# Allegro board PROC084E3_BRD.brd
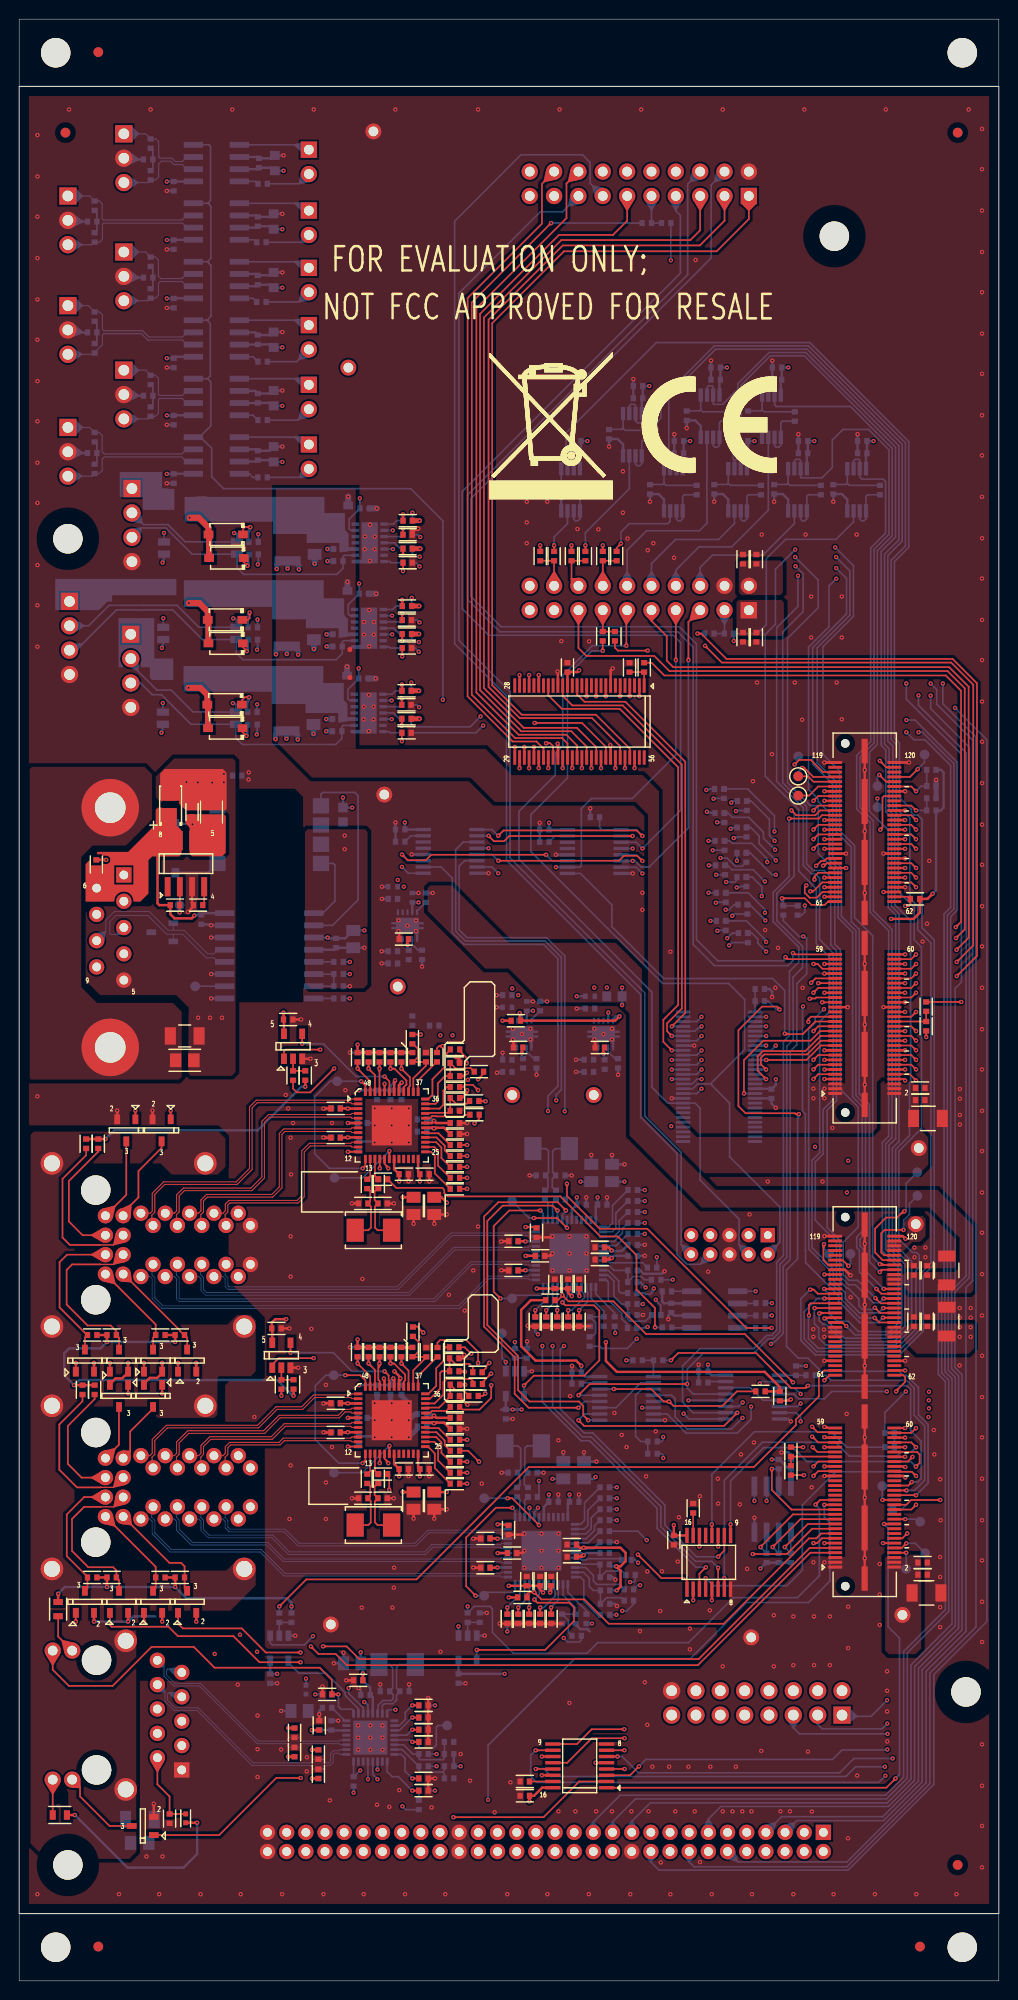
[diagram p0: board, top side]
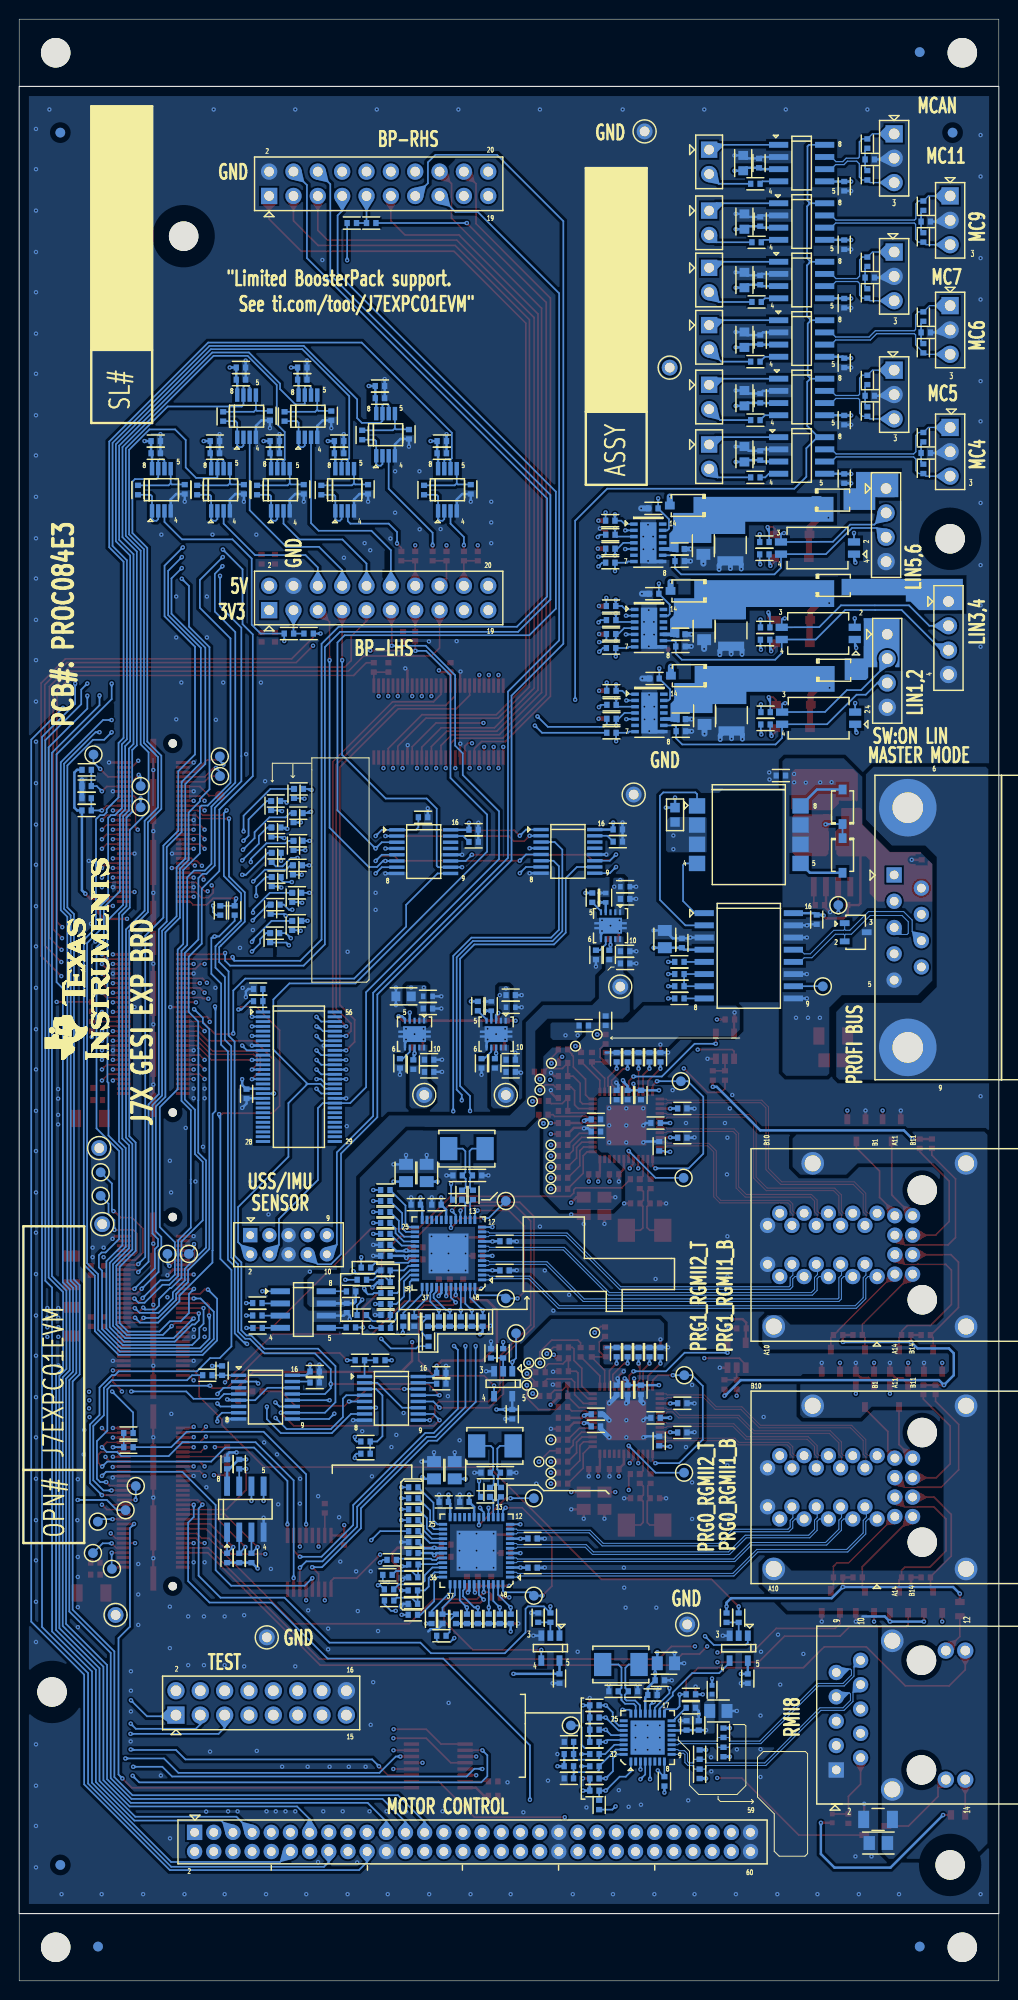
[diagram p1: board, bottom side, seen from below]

Outline 102.21 x 204.5 mm; copper layers: TOP, L02_GND1, L03_SIG1, L04_GND2, L05_PWR1, L06_SIG2, L07_GND, BOTTOM. Coordinates in mm from the lower left corner of the outline.
Outline path: rectangle 0,7 102.21,197.5 ; 0,204.5 102.21,204.5 102.21,197.5 0,197.5 0,204.5 ; 0,7 102.21,7 102.21,0 0,0 0,7

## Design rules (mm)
net group INS23889382: nets PROFIBUS_DATA_N PROFIBUS_DATA_P
net group INS23889406: nets CAN5_H CAN5_L
net group INS23889421: nets CAN6_H CAN6_L
net group INS23889438: nets CAN4_H CAN4_L
net group INS23889503: nets CAN2_H CAN2_L
net group INS23889509: nets CAN3_H CAN3_L
net group INS23889534: nets CAN1_H CAN1_L
net group INS23889562: nets PRG1_RGMII2_D0_N PRG1_RGMII2_D0_P
net group INS23889568: nets PRG1_RGMII2_D2_N PRG1_RGMII2_D2_P
net group INS23895979: nets PRG1_RGMII1_D3_N PRG1_RGMII1_D3_P
net group INS23895989: nets PRG1_RGMII1_D1_N PRG1_RGMII1_D1_P
net group INS23896047: nets PRG1_RGMII1_D0_N PRG1_RGMII1_D0_P
net group INS23896390: nets PRG0_RGMII1_D3_N PRG0_RGMII1_D3_P
net group INS23896402: nets PRG0_RGMII1_D1_N PRG0_RGMII1_D1_P
net group INS23896422: nets PRG0_RGMII1_D2_N PRG0_RGMII1_D2_P
net group INS23896856: nets PRG0_RGMII1_D0_N PRG0_RGMII1_D0_P
net group INS25431987: nets PRG1_RGMII1_D2_N PRG1_RGMII1_D2_P
net group PRG0_RGMII2_D0_: nets PRG0_RGMII2_D0_N PRG0_RGMII2_D0_P
net group PRG0_RGMII2_D1_: nets PRG0_RGMII2_D1_N PRG0_RGMII2_D1_P
net group PRG0_RGMII2_D2_: nets PRG0_RGMII2_D2_N PRG0_RGMII2_D2_P
net group PRG0_RGMII2_D3_: nets PRG0_RGMII2_D3_N PRG0_RGMII2_D3_P
net group PRG0_RGMII2_RD0: nets PRG0_RGMII2_RD0 PRG0_RGMII2_RD0_R
net group PRG1_RGMII1_RD0: nets PRG1_RGMII1_RD0 PRG1_RGMII1_RD0_R
net group PRG1_RGMII1_RD3: nets PRG1_RGMII1_RD3 PRG1_RGMII1_RD3_R
net group PRG1_RGMII2_D1_: nets PRG1_RGMII2_D1_N PRG1_RGMII2_D1_P
net group PRG1_RGMII2_D3_: nets PRG1_RGMII2_D3_N PRG1_RGMII2_D3_P
net group PRG1_RGMII2_RXC: nets PRG1_RGMII2_RXC PRG1_RGMII2_RXC_R
net group RMII8_50MHZ_REFCLK: nets RMII8_50MHZ_REFCLK RMII8_PHYAD4
net group RMII8_RXD0: nets RMII8_PHYAD1 RMII8_RXD0
net group RMII8_RXD1: nets RMII8_PHYAD2 RMII8_RXD1
net group RMII_RD: nets RMII8_MDI_RD_N RMII8_MDI_RD_P
net group RMII_TD: nets RMII8_MDI_TD_N RMII8_MDI_TD_P
net group INS23888611: nets RMII8_TXD1
net group POWER: nets PG_V2V5 V12V0_VSUP1 V12V0_VSUP2 V12V0_VSUP3 VBAT_LIN1 VBAT_LIN2 VBAT_LIN3 VPROFI_TRANSA VPROFI_TRANSB
net group PRG0_RGMII1_RD0: nets PRG0_RGMII1_RD0_R
net group PRG0_RGMII1_RD1: nets PRG0_RGMII1_RD1_R
net group PRG0_RGMII1_RD2: nets PRG0_RGMII1_RD2_R
net group PRG0_RGMII1_RD3: nets PRG0_RGMII1_RD3_R
net group PRG0_RGMII1_RX_CTL: nets PRG0_RGMII1_RX_CTL_R
net group PRG0_RGMII1_RXC: nets PRG0_RGMII1_RXC_R
net group PRG0_RGMII2_RD1: nets PRG0_RGMII2_RD1_R
net group PRG0_RGMII2_RD2: nets PRG0_RGMII2_RD2_R
net group PRG0_RGMII2_RD3: nets PRG0_RGMII2_RD3_R
net group PRG0_RGMII2_RX_CTL: nets PRG0_RGMII2_RX_CTL_R
net group PRG0_RGMII2_RXC: nets PRG0_RGMII2_RXC_R
net group PRG0_RGMII2_TD: nets PRG0_RGMII2_TD0_R PRG0_RGMII2_TD1_R PRG0_RGMII2_TD2_R PRG0_RGMII2_TD3_R PRG0_RGMII2_TX_CTL_R PRG0_RGMII2_TXC_R
net group PRG1_RGMII1_RD1: nets PRG1_RGMII1_RD1_R
net group PRG1_RGMII1_RD2: nets PRG1_RGMII1_RD2_R
net group PRG1_RGMII1_RX_CTL: nets PRG1_RGMII1_RX_CTL_R
net group PRG1_RGMII1_RXC: nets PRG1_RGMII1_RXC_R
net group PRG1_RGMII2_RD0: nets PRG1_RGMII2_RD0_R
net group PRG1_RGMII2_RD1: nets PRG1_RGMII2_RD1_R
net group PRG1_RGMII2_RD2: nets PRG1_RGMII2_RD2_R
net group PRG1_RGMII2_RD3: nets PRG1_RGMII2_RD3_R
net group PRG1_RGMII2_RX_CTL: nets PRG1_RGMII2_RX_CTL_R

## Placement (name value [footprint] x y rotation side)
C1  10uF  [CAP0402_0-75]  75.52 148.2 90 top
C2  0.1uF  [CAP0402_0-75]  76.92 148.2 270 top
C3  10uF  [CAP0402_0-75]  75.52 140.07 270 top
C4  0.1uF  [CAP0402_0-75]  76.92 140.07 90 top
C5  4.7uF_10V  [CAPT3216A_2]  15.8 122.65 90 top
C6  0.1uF  [CAP0402_0-75]  18.03 121.84 90 top
C7  10uF  [CAP0805_1-5]  20.07 121.84 90 top
C8  0.1uF  [CAP0402_0-75]  8.05 116.37 270 top
C9  0.1uF  [CAP0402_0-75]  28.07 100.22 0 top
C10  1000pF  [CAP1206_1-75]  17.27 98.5 180 top
C11  0.1uF  [CAP0402_0-75]  94.01 93.08 180 top
C12  0.1uF  [CAP0402_0-75]  94.01 91.81 180 top
C13  0.1uF  [CAP0402_0-75]  33.02 90.95 180 top
C14  22uF  [CAP1206_2]  94.82 89.91 0 top
C15  1uF  [CAP0402_0-75]  45.47 89.42 0 top
C16  1uF  [CAP0402_0-75]  45.47 88.28 0 top
C17  0.1uF  [CAP0402_0-75]  33.02 87.9 180 top
C18  0.1uF  [CAP0402_0-75]  40.13 84.09 0 top
C19  0.1uF  [CAP0402_0-75]  42.29 84.09 0 top
C20  27pF  [CAP0402_0-75]  35.89 81.04 0 top
C21  27pF  [CAP0402_0-75]  37.92 81.04 180 top
C22  10uF  [CAP0805_1-5]  41.15 80.79 270 top
C23  10uF  [CAP0805_1-5]  43.31 80.79 270 top
C24  1uF  [CAP0402_0-75]  51.56 77.1 180 top
C25  0.1uF  [CAP0402_0-75]  60.58 76.47 180 top
C26  0.1uF  [CAP0402_0-75]  54.36 75.58 0 top
C27  0.1uF  [CAP0402_0-75]  60.58 75.2 180 top
C28  1uF  [CAP0402_0-75]  51.56 74.06 180 top
C29  0.1uF  [CAP0402_0-75]  93.34 74.06 270 top
C30  0.1uF  [CAP0402_0-75]  94.74 74.06 270 top
C31  22uF  [CAP1206_2]  96.77 74.06 90 top
C32  1uF  [CAP0402_0-75]  55.88 72.66 90 top
C33  0.1uF  [CAP0402_0-75]  57.28 72.66 90 top
C34  0.1uF  [CAP0402_0-75]  58.42 72.66 90 top
C35  0.1uF  [CAP0402_0-75]  93.34 68.72 270 top
C36  0.1uF  [CAP0402_0-75]  94.74 68.72 270 top
C37  22uF  [CAP1206_2]  96.77 68.72 90 top
C38  0.1uF  [CAP0402_0-75]  26.85 68.01 0 top
C39  0.1uF  [CAP0402_0-75]  33.02 60.21 180 top
C40  1uF  [CAP0402_0-75]  45.47 58.69 0 top
C41  1uF  [CAP0402_0-75]  45.47 57.55 0 top
C42  0.1uF  [CAP0402_0-75]  33.02 57.16 180 top
C43  0.1uF  [CAP0402_0-75]  40.13 53.35 0 top
C44  0.1uF  [CAP0402_0-75]  42.29 53.35 0 top
C45  27pF  [CAP0402_0-75]  35.89 50.31 0 top
C46  27pF  [CAP0402_0-75]  37.92 50.31 180 top
C47  10uF  [CAP0805_1-5]  41.15 50.05 270 top
C48  10uF  [CAP0805_1-5]  43.31 50.05 270 top
C49  1uF  [CAP0402_0-75]  48.64 46.12 180 top
C50  0.1uF  [CAP0402_0-75]  57.66 45.48 180 top
C51  0.1uF  [CAP0402_0-75]  51.44 44.59 0 top
C52  0.1uF  [CAP0402_0-75]  57.66 44.21 180 top
C53  0.1uF  [CAP0402_0-75]  94.26 43.6 180 top
C54  1uF  [CAP0402_0-75]  48.64 43.07 180 top
C55  0.1uF  [CAP0402_0-75]  94.26 42.34 180 top
C56  1uF  [CAP0402_0-75]  52.96 41.67 90 top
C57  0.1uF  [CAP0402_0-75]  54.36 41.67 90 top
C58  0.1uF  [CAP0402_0-75]  55.5 41.67 90 top
C59  22uF  [CAP1206_2]  94.66 40.44 0 top
C60  0.01uF  [CAP0402_0-75]  35.37 31.33 180 top
C61  0.01uF  [CAP0402_0-75]  31.31 26.63 90 top
C62  4700pF  [CAP0402_0-75]  13.46 189.88 180 bottom
C63  4.7uF  [CAP0603_1]  26.67 189.5 270 bottom
C64  0.01uF  [CAP0402_0-75]  25.02 189.5 90 bottom
C65  0.1uF  [CAP0402_0-75]  16.13 187.09 270 bottom
C66  4.7uF  [CAP0603_1]  26.54 183.4 270 bottom
C67  0.01uF  [CAP0402_0-75]  24.89 183.4 90 bottom
C68  4700pF  [CAP0402_0-75]  7.62 183.4 180 bottom
C69  0.1uF  [CAP0402_0-75]  16.13 180.99 270 bottom
C70  4700pF  [CAP0402_0-75]  13.46 177.56 180 bottom
C71  4.7uF  [CAP0603_1]  26.54 177.31 270 bottom
C72  0.01uF  [CAP0402_0-75]  24.89 177.31 90 bottom
C73  0.1uF  [CAP0402_0-75]  16.13 174.89 270 bottom
C74  4700pF  [CAP0402_0-75]  7.62 171.85 180 bottom
C75  4.7uF  [CAP0603_1]  26.54 171.08 270 bottom
C76  0.01uF  [CAP0402_0-75]  24.89 171.08 90 bottom
C77  0.1uF  [CAP0402_0-75]  16.13 168.67 270 bottom
C78  0.1uF  [CAP0402_0-75]  79.07 168.19 180 bottom
C79  0.1uF  [CAP0402_0-75]  72.67 168.19 180 bottom
C80  0.01uF  [CAP0402_0-75]  79.07 166.92 180 bottom
C81  0.01uF  [CAP0402_0-75]  72.67 166.92 180 bottom
C83  0.1uF  [CAP0402_0-75]  64.57 166.26 180 bottom
C84  4700pF  [CAP0402_0-75]  13.46 165.24 180 bottom
C85  0.01uF  [CAP0402_0-75]  64.57 164.99 180 bottom
C86  4.7uF  [CAP0603_1]  26.54 164.99 270 bottom
C87  0.01uF  [CAP0402_0-75]  24.89 164.99 90 bottom
C88  0.1uF  [CAP0402_0-75]  16.13 162.7 270 bottom
C89  0.1uF  [CAP0402_0-75]  87.96 160.52 180 bottom
C90  0.1uF  [CAP0402_0-75]  81.79 160.52 180 bottom
C91  0.1uF  [CAP0402_0-75]  75.54 160.52 180 bottom
C92  0.1uF  [CAP0402_0-75]  68.83 160.52 180 bottom
C93  0.1uF  [CAP0402_0-75]  58.12 160.52 180 bottom
C94  4700pF  [CAP0402_0-75]  7.62 159.27 180 bottom
C95  0.01uF  [CAP0402_0-75]  87.96 159.25 180 bottom
C96  0.01uF  [CAP0402_0-75]  81.79 159.25 180 bottom
C97  0.01uF  [CAP0402_0-75]  75.54 159.25 180 bottom
C98  0.01uF  [CAP0402_0-75]  68.83 159.25 180 bottom
C99  0.01uF  [CAP0402_0-75]  58.12 159.25 180 bottom
C100  4.7uF  [CAP0603_1]  26.54 159.15 270 bottom
C101  0.01uF  [CAP0402_0-75]  24.89 159.02 90 bottom
C102  0.1uF  [CAP0402_0-75]  16.13 156.61 270 bottom
C107  0.1uF  [CAP0402_0-75]  39.75 120.03 180 bottom
C108  0.1uF  [CAP0402_0-75]  54.79 120 180 bottom
C109  1uF  [CAP0402_0-5]  38.99 114.06 180 bottom
C110  1uF  [CAP0402_0-5]  41.02 112.92 90 bottom
C111  0.1uF  [CAP0402_0-75]  38.99 112.79 0 bottom
C113  0.1uF  [CAP0402_0-75]  19 110.63 270 bottom
C114  10uF  [CAP0805_1-5]  34.85 108.6 270 bottom
C115  0.1uF  [CAP0402_0-75]  33.07 108.19 270 bottom
C116  10uF  [CAP0402_0-75]  38.99 107.33 180 bottom
C117  0.01uF  [CAP0402_0-75]  42.04 106.95 270 bottom
C118  0.1uF  [CAP0402_0-75]  38.99 106.06 0 bottom
C119  0.1uF  [CAP0402_0-75]  50.93 102.76 0 bottom
C120  4.7uF  [CAP0603_1]  62.1 102.63 180 bottom
C121  1uF  [CAP0402_0-5]  59.56 102.63 180 bottom
C122  1uF  [CAP0402_0-5]  52.96 101.61 90 bottom
C123  1uF  [CAP0402_0-5]  50.93 101.49 180 bottom
C124  0.1uF  [CAP0402_0-75]  59.56 101.36 0 bottom
C125  10uF  [CAP0402_0-75]  59.44 96.03 180 bottom
C126  10uF  [CAP0402_0-75]  50.93 96.03 180 bottom
C127  0.01uF  [CAP0402_0-75]  62.48 95.65 270 bottom
C128  0.01uF  [CAP0402_0-75]  53.98 95.65 270 bottom
C129  0.1uF  [CAP0402_0-75]  59.44 94.76 0 bottom
C130  0.1uF  [CAP0402_0-75]  50.93 94.76 0 bottom
C131  0.1uF  [CAP0402_0-75]  78.49 92.47 270 bottom
C132  0.1uF  [CAP0402_0-75]  39.88 92.34 270 bottom
C133  0.1uF  [CAP0402_0-75]  38.73 92.34 270 bottom
C134  1uF  [CAP0402_0-75]  37.34 92.34 270 bottom
C135  1uF  [CAP0402_0-75]  33.02 90.95 180 bottom
C136  0.1uF  [CAP0402_0-75]  42.04 89.8 180 bottom
C137  0.1uF  [CAP0402_0-75]  35.81 89.42 0 bottom
C138  0.1uF  [CAP0402_0-75]  42.04 88.53 180 bottom
C139  1uF  [CAP0402_0-75]  33.02 87.9 180 bottom
C140  10uF  [CAP0805_1-5]  61.85 84.22 90 bottom
C141  10uF  [CAP0805_1-5]  59.69 84.22 90 bottom
C142  27pF  [CAP0402_0-75]  56.46 83.96 180 bottom
C143  27pF  [CAP0402_0-75]  54.43 83.96 0 bottom
C144  0.1uF  [CAP0402_0-75]  60.83 80.91 0 bottom
C145  0.1uF  [CAP0402_0-75]  58.67 80.91 0 bottom
C146  0.1uF  [CAP0402_0-75]  51.56 77.1 180 bottom
C147  1uF  [CAP0402_0-75]  64.01 76.72 0 bottom
C148  1uF  [CAP0402_0-75]  64.01 75.58 0 bottom
C149  0.1uF  [CAP0402_0-75]  51.56 74.06 180 bottom
C150  0.1uF  [CAP0402_0-75]  68.04 70.14 270 bottom
C152  0.1uF  [CAP0402_0-75]  71.37 63.51 180 bottom
C153  0.1uF  [CAP0402_0-75]  58.17 63.39 180 bottom
C154  0.1uF  [CAP0402_0-75]  39.88 61.61 270 bottom
C155  0.1uF  [CAP0402_0-75]  38.73 61.61 270 bottom
C156  1uF  [CAP0402_0-75]  37.34 61.61 270 bottom
C157  1uF  [CAP0402_0-75]  33.02 60.21 180 bottom
C158  0.1uF  [CAP0402_0-75]  50.76 59.07 270 bottom
C159  0.1uF  [CAP0402_0-75]  42.04 59.07 180 bottom
C160  0.1uF  [CAP0402_0-75]  35.81 58.69 0 bottom
C161  0.1uF  [CAP0402_0-75]  42.04 57.8 180 bottom
C162  1uF  [CAP0402_0-75]  33.02 57.16 180 bottom
C163  0.1uF  [CAP0402_0-75]  80.52 53.86 90 bottom
C164  10uF  [CAP0805_1-5]  58.93 53.23 90 bottom
C165  10uF  [CAP0805_1-5]  56.77 53.23 90 bottom
C166  27pF  [CAP0402_0-75]  53.54 52.97 180 bottom
C167  27pF  [CAP0402_0-75]  51.51 52.97 0 bottom
C168  0.1uF  [CAP0402_0-75]  57.91 49.93 0 bottom
C169  0.1uF  [CAP0402_0-75]  55.75 49.93 0 bottom
C170  0.1uF  [CAP0402_0-75]  48.64 46.12 180 bottom
C171  1uF  [CAP0402_0-75]  61.09 45.73 0 bottom
C172  1uF  [CAP0402_0-75]  61.09 44.59 0 bottom
C173  0.1uF  [CAP0402_0-75]  48.64 43.07 180 bottom
C174  10uF  [CAP0805_1-5]  34.73 33.1 180 bottom
C175  0.1uF  [CAP0402_0-75]  45.84 31.51 270 bottom
C176  0.1uF  [CAP0402_0-75]  26.19 31.5 270 bottom
C177  1000pF  [CAP0402_0-75]  35.37 31.33 180 bottom
C178  27pF  [CAP0402_0-75]  40.2 30.18 180 bottom
C179  27pF  [CAP0402_0-75]  38.16 30.18 0 bottom
C180  100pF  [CAP0402_0-75]  36.13 29.8 180 bottom
C181  10uF  [CAP0805_1-5]  29.26 28.13 180 bottom
C182  100pF  [CAP0402_0-75]  32.58 26.63 90 bottom
C183  1000pF  [CAP0402_0-75]  31.31 26.63 90 bottom
C184  1000pF  [CAP1206_1-75]  12.6 16.82 180 bottom
C185  0.1uF  [CAP0402_0-75]  57.21 136.92 90 top
C186  1uF  [CAP0402_0-75]  28.73 25.86 270 top
C187  0.1uF  [CAP0402_0-75]  28.73 23.85 270 top
C188  0.1uF  [CAP0402_0-75]  31.22 21.58 270 top
C189  1uF  [CAP0402_0-75]  31.22 23.59 270 top
C190  1uF  [CAP0402_0-75]  15.69 16.91 270 top
C191  0.1uF  [CAP0402_0-75]  68.3 45.94 270 top
C192  0.1uF  [CAP0402_0-75]  52.76 19.29 180 top
C193  0.1uF  [CAP0402_0-75]  33.19 131.54 180 bottom
C194  1uF  [CAP0805_1-5]  30.71 131.88 270 bottom
C195  10uF  [CAP1210_2-75]  27.89 131.95 270 bottom
C196  220pF  [CAP0402_0-75]  35.92 135.77 0 bottom
C197  220pF  [CAP0402_0-75]  33.18 130.27 180 bottom
C198  0.1uF  [CAP0402_0-75]  33.23 140.37 180 bottom
C199  1uF  [CAP0805_1-5]  30.75 140.71 270 bottom
C200  10uF  [CAP1210_2-75]  27.93 140.78 270 bottom
C201  220pF  [CAP0402_0-75]  35.96 144.6 0 bottom
C202  220pF  [CAP0402_0-75]  33.22 139.11 180 bottom
C203  0.1uF  [CAP0402_0-75]  33.31 149.27 180 bottom
C204  1uF  [CAP0805_1-5]  30.83 149.61 270 bottom
C205  10uF  [CAP1210_2-75]  28.01 149.68 270 bottom
C206  220pF  [CAP0402_0-75]  36.04 153.5 0 bottom
C207  220pF  [CAP0402_0-75]  33.3 148.01 180 bottom
D4  MBR0520L  [DIO_SOD123]  16.31 122.39 90 bottom
D5  MBR0520L  [DIO_SOD123]  16.31 117.31 270 bottom
D6  SM712.TCT  [DIO_SOT23_123]  14.94 109.31 180 bottom
D7  1N4148W-7-F  [DIO_SOD123_1-4]  21.5 130.59 180 top
D8  1N4148W-7-F  [DIO_SOD123_1-4]  32.41 136.07 0 bottom
D9  1N4148W-7-F  [DIO_SOD123_1-4]  21.44 133.04 180 top
D10  1N4148W-7-F  [DIO_SOD123_1-4]  17.1 136.63 180 bottom
D11  1N4148W-7-F  [DIO_SOD123_1-4]  21.54 139.43 180 top
D12  1N4148W-7-F  [DIO_SOD123_1-4]  32.45 144.9 0 bottom
D13  1N4148W-7-F  [DIO_SOD123_1-4]  21.48 141.88 180 top
D14  1N4148W-7-F  [DIO_SOD123_1-4]  17.14 145.47 180 bottom
D15  1N4148W-7-F  [DIO_SOD123_1-4]  21.62 148.32 180 top
D16  1N4148W-7-F  [DIO_SOD123_1-4]  32.53 153.8 0 bottom
D17  1N4148W-7-F  [DIO_SOD123_1-4]  21.55 150.78 180 top
D18  1N4148W-7-F  [DIO_SOD123_1-4]  17.22 154.37 180 bottom
FL1  120E  [EMIFIL_BLM18A_0603]  33.78 121.55 270 bottom
FL2  120E  [EMIFIL_BLM15A_0402_0-6]  29.92 30.34 270 bottom
FL3  120E  [EMIFIL_BLM15A_0402_0-6]  17.37 16.94 270 top
J1  CON_PMC_2X60_M  [CON_PMC2X60_QTH-60-1-D-A_P_S_S_4-4]  88.22 109.76 90 top
J2  CON_PMC_2X60_M  [CON_PMC2X60_QTH-60-1-D-A_P_S_S_4-4]  88.22 60.38 90 top
J3  HDR_1X3  [HDR_3X1_100_S_T]  10.92 192.55 90 bottom
J4  HDR_1X2  [HDR_1X2_68002-202_S_T_8-6]  30.23 190.9 90 bottom
J5  HDR_2X10  [HDR_2X10_TSW_100_S_T]  76.13 186.07 0 bottom
J6  HDR_1X3  [HDR_3X1_100_S_T]  5.08 186.07 90 bottom
J7  HDR_1X2  [HDR_1X2_68002-202_S_T_8-6]  30.23 184.55 90 bottom
J8  HDR_1X3  [HDR_3X1_100_S_T]  10.92 180.23 90 bottom
J9  HDR_1X2  [HDR_1X2_68002-202_S_T_8-6]  30.23 178.58 90 bottom
J10  HDR_1X3  [HDR_3X1_100_S_T]  5.08 174.64 90 bottom
J11  HDR_1X2  [HDR_1X2_68002-202_S_T_8-6]  30.23 172.61 90 bottom
J12  HDR_1X3  [HDR_3X1_100_S_T]  10.92 167.91 90 bottom
J13  HDR_1X2  [HDR_1X2_68002-202_S_T_8-6]  30.23 166.38 90 bottom
J14  HDR_1X3  [HDR_3X1_100_S_T]  5.08 161.94 90 bottom
J15  HDR_1X2  [HDR_1X2_68002-202_S_T_8-6]  30.23 160.16 90 bottom
J16  HDR_2X10  [HDR_2X10_TSW_100_S_T]  76.13 142.89 0 bottom
J18  CON_DSUB_9_S  [CON_DB9_D09S33E4GV_S_R_T]  10.92 115.28 90 bottom
J19  RECP_2X5  [RECPT_2X5_NPPN052AFCN_S_T_4-3]  78.11 77.74 180 bottom
J20  CON_RJ45-28_LPJG17512AONL  [CON_RJ45-28_LPJG17512_S_R_T_25-3]  12.7 73.42 90 bottom
J21  CON_RJ45-28_LPJG17512AONL  [CON_RJ45-28_LPJG17512_S_R_T_25-3]  12.7 48.15 90 bottom
J22  HDR_8X2  [HDR_8X2_100_S_T]  85.85 27.7 0 bottom
J23  CON_RJ45-14_LPJG16314A4NL  [CON_RJ45-14_LPJG16314A4NL_S_R_T_13-6]  16.96 21.99 90 bottom
J24  RECP_30X2  [RECPT_2X30_78-74_S_T]  83.91 15.48 0 bottom
J25  HDR_1X4  [HDR_1X4_61300411121_S_T_8-6]  11.64 140.38 90 bottom
J26  HDR_1X4  [HDR_1X4_61300411121_S_T_8-6]  5.25 143.8 90 bottom
J27  HDR_1X4  [HDR_1X4_61300411121_S_T_8-6]  11.76 155.57 90 bottom
NOREF  -  []  91.63 -76.11 0 top
NOREF#2  -  []  102.21 7 90 top
NOREF#3  -  [unnamed#2]  8.26 3.57 0 top
NOREF#4  -  [unnamed#2]  97.92 12.08 0 top
NOREF#5  -  []  323.62 104.43 0 top
NOREF#6  -  []  0 204.5 0 top
NOREF#7  -  [unnamed#2]  93.98 3.57 0 top
NOREF#8  -  [unnamed#2]  98.4 201 270 top
NOREF#9  -  []  102.21 0 90 top
NOREF#10  -  []  28.19 145.68 0 top
NOREF#11  -  []  -130.43 -16.24 0 top
NOREF#12  -  [unnamed#2]  97.92 192.67 0 top
NOREF#13  -  [unnamed#2]  8.26 201.07 0 top
NOREF#14  -  []  0 6.95 0 top
NOREF#15  -  [unnamed#2]  98.4 3.5 270 top
NOREF#16  -  [unnamed#2]  3.81 3.5 270 top
NOREF#17  -  [unnamed#2]  3.81 201 270 top
NOREF#18  -  []  31.75 -88.89 0 top
NOREF#19  -  [unnamed#2]  4.83 192.67 0 top
NOREF#20  -  [unnamed#2]  5.08 150.33 180 top
NOREF#21  -  []  0 197.6 0 top
NOREF#22  -  []  -504.19 -64.76 0 top
NOREF#23  -  [unnamed#2]  98.78 30.11 0 top
NOREF#24  -  [unnamed#2]  5.08 12.08 270 top
NOREF#25  -  [unnamed#2]  85.05 181.88 90 top
NOREF#26  -  [unnamed#2]  8.26 3.57 180 bottom
NOREF#27  -  [unnamed#2]  93.98 3.57 180 bottom
NOREF#28  -  [unnamed#2]  8.26 201.07 180 bottom
NOREF#29  -  []  98.83 133.21 90 bottom
NOREF#30  -  []  105.92 16.45 90 bottom
NOREF#31  -  [unnamed#2]  97.92 192.67 180 bottom
NOREF#32  -  [unnamed#2]  4.83 192.67 180 bottom
NOREF#33  -  [unnamed#2]  97.92 12.08 180 bottom
NOREF#34  -  []  47.24 126.77 90 bottom
Q1  BSS138-7-F  [SOT23-123_1-1]  11.18 88.66 270 top
Q2  BSS138-7-F  [SOT23-123_1-1]  14.86 88.66 270 top
Q3  BSS138-7-F  [SOT23-123_1-1]  6.86 64.66 90 top
Q4  BSS138-7-F  [SOT23-123_1-1]  10.41 64.66 90 top
Q5  BSS138-7-F  [SOT23-123_1-1]  13.97 64.66 90 top
Q6  BSS138-7-F  [SOT23-123_1-1]  17.53 64.66 90 top
Q7  BSS138-7-F  [SOT23-123_1-1]  10.41 60.97 270 top
Q8  BSS138-7-F  [SOT23-123_1-1]  13.97 60.97 270 top
Q9  BSS138-7-F  [SOT23-123_1-1]  6.86 39.51 90 top
Q10  BSS138-7-F  [SOT23-123_1-1]  10.41 39.51 90 top
Q11  BSS138-7-F  [SOT23-123_1-1]  13.97 39.51 90 top
Q12  BSS138-7-F  [SOT23-123_1-1]  17.53 39.51 90 top
Q13  BSS138-7-F  [SOT23-123_1-1]  12.9 16.14 180 top
R1  0E  [RES0402_0-5]  60.88 140.17 90 top
R2  0E  [RES0402_0-5]  62.15 140.17 90 top
R3  10K  [RES0402_0-5]  93.47 112.79 0 top
R4  100K  [RES0402_0-5]  16.26 112.14 180 top
R5  10K  [RES0402_0-5]  18.67 112.14 180 top
R6  2.87K_1%  [RES0402_0-5]  40.13 108.6 180 top
R7  10K  [RES0402_0-5]  51.82 100.09 0 top
R8  1.69K_1%  [RES0402_0-5]  52.07 97.3 180 top
R9  4.53K_1%  [RES0402_0-5]  60.58 97.3 180 top
R10  10K_1%  [RES0402_0-5]  35.31 96.28 270 top
R11  10K_1%  [RES0402_0-5]  36.45 96.28 270 top
R12  10K_1%  [RES0402_0-5]  37.59 96.28 270 top
R13  5.76K_1%  [RES0402_0-5]  38.73 96.28 270 top
R14  5.76K_1%  [RES0402_0-5]  39.88 96.28 270 top
R15  5.76K_1%  [RES0402_0-5]  41.02 96.28 270 top
R16  0E_1%  [RES0402_0-5]  41.02 98.16 270 top
R17  0E_1%  [RES0402_0-5]  43.59 96.29 270 top
R18  1M_1%  [RES0805_0-75]  17.27 95.96 180 top
R19  0E_1%  [RES0402_0-5]  45.48 97.1 180 top
R20  0E  [RES0402_0-5]  28.57 94.38 90 top
R21  10K  [RES0402_0-5]  29.84 94.38 270 top
R22  0E_1%  [RES0402_0-5]  47.97 94.78 180 top
R23  0E_1%  [RES0402_0-5]  45.47 93.17 180 top
R24  0E_1%  [RES0402_0-5]  47.48 91.72 180 top
R25  0E_1%  [RES0402_0-5]  47.51 90.29 180 top
R26  220E_1%  [RES0402_0-5]  6.99 87.26 270 top
R27  220E_1%  [RES0402_0-5]  8.26 87.26 270 top
R28  0E_1%  [RES0402_0-5]  45.47 87.14 180 top
R29  0E_1%  [RES0402_0-5]  45.47 85.99 180 top
R30  0E_1%  [RES0402_0-5]  45.47 84.85 180 top
R31  0E_1%  [RES0402_0-5]  45.47 83.71 180 top
R32  0E  [RES0402_0-5]  37.95 83.56 180 top
R33  0E  [RES0402_0-5]  36.32 83.07 90 top
R34  0E  [RES0402_0-5]  37.47 83.07 90 top
R35  0E_1%  [RES0402_0-5]  45.47 82.56 180 top
R36  11K_1%  [RES0402_0-5]  53.98 77.99 90 top
R37  2.49K_1%  [RES0402_0-5]  63.99 74.06 0 bottom
R38  10K_1%  [RES0402_0-5]  63.97 72.84 180 bottom
R39  2.49K_1%  [RES0402_0-5]  63.97 70.56 180 bottom
R40  2.49K_1%  [RES0402_0-5]  63.97 69.41 0 bottom
R41  10K  [RES0402_0-5]  55.42 70.96 180 top
R42  2.49K_1%  [RES0402_0-5]  53.85 68.72 270 top
R43  2.49K_1%  [RES0402_0-5]  54.99 68.72 270 top
R44  2.49K_1%  [RES0402_0-5]  56.13 68.72 270 top
R45  2.49K_1%  [RES0402_0-5]  57.28 68.72 270 top
R46  2.49K_1%  [RES0402_0-5]  58.42 68.72 270 top
R47  2.49K_1%  [RES0402_0-5]  60.99 68.73 270 bottom
R48  220E_1%  [RES0402_0-5]  7.62 67.32 180 top
R49  220E_1%  [RES0402_0-5]  9.65 67.32 0 top
R50  220E_1%  [RES0402_0-5]  14.73 67.32 180 top
R51  220E_1%  [RES0402_0-5]  16.76 67.32 0 top
R52  10K_1%  [RES0402_0-5]  35.31 65.55 270 top
R53  10K_1%  [RES0402_0-5]  36.45 65.55 270 top
R54  10K_1%  [RES0402_0-5]  37.59 65.55 270 top
R55  5.76K_1%  [RES0402_0-5]  38.73 65.55 270 top
R56  5.76K_1%  [RES0402_0-5]  39.88 65.55 270 top
R57  5.76K_1%  [RES0402_0-5]  41.02 65.55 270 top
R58  0E_1%  [RES0402_0-5]  41.08 67.67 270 top
R59  0E_1%  [RES0402_0-5]  43.64 65.53 270 top
R60  0E_1%  [RES0402_0-5]  45.39 66.04 180 top
R61  0E_1%  [RES0402_0-5]  47.82 63.44 180 top
R62  0E  [RES0402_0-5]  27.36 62.17 90 top
R63  10K  [RES0402_0-5]  28.63 62.17 270 top
R64  0E_1%  [RES0402_0-5]  47.84 62.21 180 top
R65  220E_1%  [RES0402_0-5]  6.6 61.61 270 top
R66  220E_1%  [RES0402_0-5]  7.87 61.61 270 top
R67  0E_1%  [RES0402_0-5]  47.4 60.98 180 top
R68  0E_1%  [RES0402_0-5]  45.47 59.83 180 top
R69  0E_1%  [RES0402_0-5]  45.47 56.4 180 top
R70  0E_1%  [RES0402_0-5]  45.47 55.26 180 top
R71  0E_1%  [RES0402_0-5]  45.47 54.12 180 top
R72  0E_1%  [RES0402_0-5]  45.47 52.97 180 top
R73  0E  [RES0402_0-5]  37.95 52.83 180 top
R74  0E  [RES0402_0-5]  36.32 52.34 90 top
R75  0E  [RES0402_0-5]  37.47 52.34 90 top
R76  0E_1%  [RES0402_0-5]  45.47 51.83 180 top
R77  11K_1%  [RES0402_0-5]  51.05 47 90 top
R78  2.49K_1%  [RES0402_0-5]  61.11 42.07 0 bottom
R79  10K_1%  [RES0402_0-5]  61.08 43.41 180 bottom
R80  220E_1%  [RES0402_0-5]  7.62 42.05 180 top
R81  220E_1%  [RES0402_0-5]  9.65 42.05 0 top
R82  220E_1%  [RES0402_0-5]  14.73 42.05 180 top
R83  220E_1%  [RES0402_0-5]  16.76 42.05 0 top
R84  10K_1%  [RES0402_0-5]  61.13 40.7 180 bottom
R85  2.49K_1%  [RES0402_0-5]  61.13 39.3 0 bottom
R86  10K  [RES0402_0-5]  52.5 39.97 180 top
R87  220E  [RES0603_0-75]  4.06 38.75 270 top
R88  2.49K_1%  [RES0402_0-5]  50.93 37.73 270 top
R89  2.49K_1%  [RES0402_0-5]  52.07 37.73 270 top
R90  2.49K_1%  [RES0402_0-5]  53.21 37.73 270 top
R91  2.49K_1%  [RES0402_0-5]  54.36 37.73 270 top
R92  2.49K_1%  [RES0402_0-5]  55.5 37.73 270 top
R93  2.49K_1%  [RES0402_0-5]  58.04 37.73 270 bottom
R94  1.96K_1%  [RES0402_0-5]  32.13 29.86 180 top
R95  2.49K_1%  [RES0402_0-5]  42.19 28.72 0 top
R96  1.96K_1%  [RES0402_0-5]  42.19 27.45 0 top
R97  1.96K_1%  [RES0402_0-5]  42.19 26.18 0 top
R98  1.96K_1%  [RES0402_0-5]  42.19 24.91 0 top
R99  1.96K_1%  [RES0402_0-5]  44.85 24.91 0 bottom
R100  2.49K_1%  [RES0402_0-5]  44.86 21.1 0 bottom
R101  2.49K_1%  [RES0402_0-5]  42.19 21.1 0 top
R102  2.49K_1%  [RES0402_0-5]  42.19 19.83 0 top
R103  220E  [RES0603_0-75]  4.24 17.29 180 top
R105  59E_1%  [RES0402_0-5]  13.72 191.53 270 bottom
R106  59E_1%  [RES0402_0-5]  13.72 188.23 270 bottom
R107  33E  [RES0402_0-5]  25.4 187.34 180 bottom
R108  59E_1%  [RES0402_0-5]  7.87 185.05 270 bottom
R109  59E_1%  [RES0402_0-5]  7.87 181.75 270 bottom
R110  33E  [RES0402_0-5]  25.27 181.24 180 bottom
R111  59E_1%  [RES0402_0-5]  13.72 179.21 270 bottom
R112  59E_1%  [RES0402_0-5]  13.72 175.91 270 bottom
R113  33E  [RES0402_0-5]  25.27 175.02 180 bottom
R114  59E_1%  [RES0402_0-5]  7.87 173.5 270 bottom
R115  59E_1%  [RES0402_0-5]  7.87 170.19 270 bottom
R117  33E  [RES0402_0-5]  25.4 168.8 180 bottom
R118  59E_1%  [RES0402_0-5]  13.72 166.89 270 bottom
R121  59E_1%  [RES0402_0-5]  13.72 163.59 270 bottom
R122  1.8K_1%  [RES0402_0-5]  76.05 163.16 270 bottom
R123  1.8K_1%  [RES0402_0-5]  69.65 163.16 270 bottom
R124  1.5K  [RES0402_0-5]  80.92 163.08 90 bottom
R125  1.5K  [RES0402_0-5]  74.52 163.08 90 bottom
R126  33E  [RES0402_0-5]  25.4 162.7 180 bottom
R127  1.8K_1%  [RES0402_0-5]  61.54 161.23 270 bottom
R128  1.5K  [RES0402_0-5]  66.42 161.15 90 bottom
R129  59E_1%  [RES0402_0-5]  7.87 160.92 270 bottom
R130  59E_1%  [RES0402_0-5]  7.87 157.62 270 bottom
R131  33E  [RES0402_0-5]  25.4 156.73 180 bottom
R132  1.8K_1%  [RES0402_0-5]  84.94 155.49 270 bottom
R133  1.8K_1%  [RES0402_0-5]  78.77 155.49 270 bottom
R134  1.8K_1%  [RES0402_0-5]  72.52 155.49 270 bottom
R135  1.8K_1%  [RES0402_0-5]  65.81 155.49 270 bottom
R136  1.8K_1%  [RES0402_0-5]  55.09 155.49 270 bottom
R137  1.5K  [RES0402_0-5]  89.81 155.41 90 bottom
R138  1.5K  [RES0402_0-5]  83.64 155.41 90 bottom
R139  1.5K  [RES0402_0-5]  77.39 155.41 90 bottom
R140  1.5K  [RES0402_0-5]  70.69 155.41 90 bottom
R141  1.5K  [RES0402_0-5]  59.97 155.41 90 bottom
R144  10K  [RES0402_0-5]  95.17 126.24 0 bottom
R148  0E  [RES0402_0-5]  74.07 140.45 180 bottom
R149  0E  [RES0402_0-5]  72.01 140.45 0 bottom
R150  10K  [RES0402_0-5]  95.17 124.55 180 bottom
R151  10K  [RES0402_0-5]  95.17 123.28 180 bottom
R152  10K  [RES0402_0-5]  95.17 122.01 0 bottom
R154  10K  [RES0402_0-5]  60.07 121.3 180 bottom
R156  10K  [RES0402_0-5]  39.75 118.76 0 bottom
R157  10K  [RES0402_0-5]  54.79 118.73 0 bottom
R158  0E  [RES0402_0-5]  22.74 125.65 180 bottom
R159  10K  [RES0402_0-5]  42.42 112.92 90 bottom
R160  3.57K_1%  [RES0402_0-5]  40.64 106.95 90 bottom
R161  0E  [RES0402_0-5]  33.32 106.22 180 bottom
R162  0E  [RES0402_0-5]  33.32 104.95 180 bottom
R163  100K  [RES0402_0-5]  33.32 103.68 0 bottom
R164  10K  [RES0402_0-5]  77.27 103.4 0 bottom
R165  0E  [RES0402_0-5]  33.32 102.41 180 bottom
R166  10K  [RES0402_0-5]  54.36 101.61 270 bottom
R167  0E  [RES0402_0-5]  77.27 102.13 0 bottom
R168  0E  [RES0402_0-5]  41.02 100.09 90 bottom
R169  0E  [RES0402_0-5]  43.31 99.58 0 bottom
R170  2.49K_1%  [RES0402_0-5]  42.45 96.29 90 top
R171  2.49K_1%  [RES0402_0-5]  39.88 96.28 90 bottom
R172  2.49K_1%  [RES0402_0-5]  38.73 96.28 90 bottom
R173  2.49K_1%  [RES0402_0-5]  37.59 96.28 90 bottom
R174  2.49K_1%  [RES0402_0-5]  36.45 96.28 90 bottom
R175  2.49K_1%  [RES0402_0-5]  35.31 96.28 90 bottom
R176  3.57K_1%  [RES0402_0-5]  52.58 95.65 90 bottom
R177  1.13K_1%  [RES0402_0-5]  61.09 95.52 90 bottom
R178  2.49K_1%  [RES0402_0-5]  45.46 95.69 0 top
R179  2.49K_1%  [RES0402_0-5]  45.47 94.32 180 top
R180  2.49K_1%  [RES0402_0-5]  45.47 92.03 180 top
R181  2.49K_1%  [RES0402_0-5]  45.46 90.69 0 top
R182  11K_1%  [RES0402_0-5]  35.43 87.01 270 bottom
R183  0E_1%  [RES0402_0-5]  64.01 82.44 180 bottom
R184  0E  [RES0402_0-5]  56.01 81.93 270 bottom
R185  0E  [RES0402_0-5]  54.86 81.93 270 bottom
R186  0E  [RES0402_0-5]  56.5 81.44 180 bottom
R187  0E_1%  [RES0402_0-5]  64.01 81.29 180 bottom
R188  0E_1%  [RES0402_0-5]  64.01 80.15 180 bottom
R189  0E_1%  [RES0402_0-5]  64.01 79.01 180 bottom
R190  0E_1%  [RES0402_0-5]  64.01 77.87 180 bottom
R191  0E_1%  [RES0402_0-5]  66.03 74.35 180 bottom
R192  0E_1%  [RES0402_0-5]  66.46 73.09 180 bottom
R193  0E_1%  [RES0402_0-5]  63.97 71.7 180 bottom
R194  10K  [RES0402_0-5]  67.58 71.87 180 bottom
R195  0E_1%  [RES0402_0-5]  66.47 69.41 180 bottom
R196  33E  [RES0402_0-5]  77.36 70.65 0 bottom
R197  0E_1%  [RES0402_0-5]  63.96 68.06 180 bottom
R198  33E  [RES0402_0-5]  77.36 69.36 0 bottom
R199  0E_1%  [RES0402_0-5]  62.13 68.73 90 bottom
R200  0E_1%  [RES0402_0-5]  59.5 66.65 90 bottom
R201  5.76K_1%  [RES0402_0-5]  59.56 68.72 90 bottom
R202  5.76K_1%  [RES0402_0-5]  58.42 68.72 90 bottom
R203  5.76K_1%  [RES0402_0-5]  57.28 68.72 90 bottom
R204  10K_1%  [RES0402_0-5]  56.13 68.72 90 bottom
R205  10K_1%  [RES0402_0-5]  54.99 68.72 90 bottom
R206  10K_1%  [RES0402_0-5]  53.85 68.72 90 bottom
R207  33E  [RES0402_0-5]  67.6 68.11 180 bottom
R208  33E  [RES0402_0-5]  77.33 68.06 0 bottom
R209  2.49K_1%  [RES0402_0-5]  42.47 65.53 90 top
R210  2.49K_1%  [RES0402_0-5]  39.88 65.55 90 bottom
R211  2.49K_1%  [RES0402_0-5]  38.73 65.55 90 bottom
R212  2.49K_1%  [RES0402_0-5]  37.59 65.55 90 bottom
R213  2.49K_1%  [RES0402_0-5]  36.45 65.55 90 bottom
R214  2.49K_1%  [RES0402_0-5]  35.31 65.55 90 bottom
R215  10K  [RES0402_0-5]  81.04 63.61 90 bottom
R216  10K  [RES0402_0-5]  52.98 65.42 270 bottom
R217  0E  [RES0402_0-5]  51.71 65.42 270 bottom
R218  2.49K_1%  [RES0402_0-5]  45.39 64.9 0 top
R219  0E  [RES0402_0-5]  82.58 63.13 180 bottom
R220  10K  [RES0402_0-5]  71.37 62.37 180 bottom
R221  10K  [RES0402_0-5]  58.17 62.24 180 bottom
R222  10K_1%  [RES0402_0-5]  45.4 63.55 180 top
R223  2.49K_1%  [RES0402_0-5]  45.47 62.15 180 top
R224  2.49K_1%  [RES0402_0-5]  45.47 60.98 0 top
R225  0E  [RES0402_0-5]  66.08 54.95 180 bottom
R226  0E  [RES0402_0-5]  66.08 56.22 180 bottom
R227  11K_1%  [RES0402_0-5]  35.43 56.28 270 bottom
R228  10K  [RES0402_0-5]  79.25 53.86 270 bottom
R229  0E_1%  [RES0402_0-5]  61.09 51.45 180 bottom
R230  0E  [RES0402_0-5]  53.09 50.94 270 bottom
R231  0E  [RES0402_0-5]  51.94 50.94 270 bottom
R232  0E  [RES0402_0-5]  53.58 50.45 180 bottom
R233  0E_1%  [RES0402_0-5]  61.09 50.31 180 bottom
R234  0E_1%  [RES0402_0-5]  61.09 49.16 180 bottom
R235  0E_1%  [RES0402_0-5]  61.09 48.02 180 bottom
R236  0E_1%  [RES0402_0-5]  61.09 46.88 180 bottom
R237  10K  [RES0402_0-5]  80.52 44.08 90 bottom
R238  10K  [RES0402_0-5]  79.25 44.08 90 bottom
R239  10K  [RES0402_0-5]  77.98 44.08 90 bottom
R240  0E_1%  [RES0402_0-5]  63.34 43.89 180 bottom
R241  0E_1%  [RES0402_0-5]  63.78 42.32 180 bottom
R242  0E_1%  [RES0402_0-5]  63.62 40.81 180 bottom
R243  0E_1%  [RES0402_0-5]  63.61 39.64 180 bottom
R244  0E_1%  [RES0402_0-5]  61.13 38.16 180 bottom
R245  10K  [RES0402_0-5]  48.06 37.86 270 bottom
R246  0E  [RES0402_0-5]  46.79 37.86 270 bottom
R247  10K  [RES0402_0-5]  28.41 37.85 90 bottom
R248  0E  [RES0402_0-5]  27.14 37.85 270 bottom
R249  0E_1%  [RES0402_0-5]  59.19 37.73 90 bottom
R250  0E_1%  [RES0402_0-5]  58.16 35.97 180 bottom
R251  5.76K_1%  [RES0402_0-5]  56.64 37.73 90 bottom
R252  5.76K_1%  [RES0402_0-5]  55.5 37.73 90 bottom
R253  5.76K_1%  [RES0402_0-5]  54.36 37.73 90 bottom
R254  10K_1%  [RES0402_0-5]  53.21 37.73 90 bottom
R255  10K_1%  [RES0402_0-5]  52.07 37.73 90 bottom
R256  10K_1%  [RES0402_0-5]  50.93 37.73 90 bottom
R257  13K_1%  [RES0402_0-5]  32.13 29.86 0 bottom
R258  5.76K_1%  [RES0402_0-5]  42.19 28.72 180 bottom
R259  4.87K_1%  [RES0402_0-5]  32.13 28.46 180 bottom
R260  13K_1%  [RES0402_0-5]  42.19 27.45 180 bottom
R261  13K_1%  [RES0402_0-5]  42.19 26.18 180 bottom
R262  13K_1%  [RES0402_0-5]  42.19 24.91 180 bottom
R263  2.49K_1%  [RES0402_0-5]  44.86 23.64 180 bottom
R264  22E_1%  [RES0402_0-5]  42.19 23.64 180 bottom
R265  2.49K_1%  [RES0402_0-5]  44.86 22.37 180 bottom
R266  22E_1%  [RES0402_0-5]  42.19 22.37 180 bottom
R267  10K  [RES0402_0-5]  42.19 21.1 0 bottom
R268  22E_1%  [RES0402_0-5]  41.7 18.34 90 bottom
R269  2.2K_1%  [RES0402_0-5]  34.89 20.79 270 bottom
R270  2.49K_1%  [RES0402_0-5]  42.19 19.83 180 bottom
R271  1M_1%  [RES0805_0-75]  12.57 14.37 180 bottom
R273  0E  [RES0402_0-5]  65.21 136.92 90 top
R274  0E  [RES0402_0-5]  55.81 148.53 90 top
R275  0E  [RES0402_0-5]  54.36 148.53 90 top
R276  0E  [RES0402_0-5]  80.52 55.14 90 top
R277  0E  [RES0402_0-5]  80.52 53.21 270 top
R278  0E  [RES0402_0-5]  59.07 148.53 90 top
R279  0E  [RES0402_0-5]  57.63 148.53 90 top
R280  0E  [RES0402_0-5]  62.34 148.53 90 top
R281  0E  [RES0402_0-5]  60.89 148.53 90 top
R282  10K  [RES0402_0-5]  63.68 136.92 90 top
R283  0E  [RES0402_0-5]  65.48 183.25 0 bottom
R284  0E  [RES0402_0-5]  67.5 183.25 180 bottom
R285  0E  [RES0402_0-5]  94.63 101.56 270 top
R286  0E  [RES0402_0-5]  94.63 99.52 270 top
R287  2.2K_1%  [RES0402_0-5]  79.36 60.96 90 top
R288  2.2K_1%  [RES0402_0-5]  77.34 61.45 0 top
R289  49.9E_1%  [RES0402_0-5]  28.73 25.86 270 bottom
R290  49.9E_1%  [RES0402_0-5]  28.73 23.85 90 bottom
R291  49.9E_1%  [RES0402_0-5]  31.22 23.59 270 bottom
R292  49.9E_1%  [RES0402_0-5]  31.22 21.58 90 bottom
R294  10K  [RES0402_0-5]  70.32 49.27 270 top
R295  0E  [RES0402_0-5]  90.81 55.63 0 bottom
R296  0E  [RES0402_0-5]  90.81 57.11 180 bottom
R297  10K  [RES0402_0-5]  52.76 20.78 0 top
R298  0E  [RES0402_0-5]  66.66 64.69 180 bottom
R299  10K  [RES0402_0-5]  64.53 64.69 180 bottom
R300  0E  [RES0402_0-5]  79.73 111.58 270 bottom
R301  0E  [RES0402_0-5]  81.22 111.58 270 bottom
R338  0E_1%  [RES0402_0-5]  73.05 124.25 180 bottom
R339  0E_1%  [RES0402_0-5]  75.43 122.99 180 bottom
R340  0E_1%  [RES0402_0-5]  73.09 121.73 180 bottom
R341  0E_1%  [RES0402_0-5]  75.4 120.24 180 bottom
R342  0E_1%  [RES0402_0-5]  73.1 118.84 180 bottom
R343  0E_1%  [RES0402_0-5]  75.38 117.59 180 bottom
R344  0E_1%  [RES0402_0-5]  73.16 116.29 180 bottom
R345  0E_1%  [RES0402_0-5]  75.37 115.07 180 bottom
R346  0E_1%  [RES0402_0-5]  73.23 113.42 180 bottom
R347  0E_1%  [RES0402_0-5]  75.49 112.19 180 bottom
R348  0E_1%  [RES0402_0-5]  73.23 110.49 180 bottom
R349  0E_1%  [RES0402_0-5]  75.53 109.22 180 bottom
R350  0E_1%  [RES0402_0-5]  73.54 123.76 270 bottom
R351  0E_1%  [RES0402_0-5]  75.92 122.5 270 bottom
R352  0E_1%  [RES0402_0-5]  73.58 121.24 270 bottom
R353  0E_1%  [RES0402_0-5]  75.89 119.75 270 bottom
R354  0E_1%  [RES0402_0-5]  73.59 118.35 270 bottom
R355  0E_1%  [RES0402_0-5]  75.87 117.1 270 bottom
R356  0E_1%  [RES0402_0-5]  73.65 115.8 270 bottom
R357  0E_1%  [RES0402_0-5]  75.86 114.58 270 bottom
R358  0E_1%  [RES0402_0-5]  73.72 112.93 270 bottom
R359  0E_1%  [RES0402_0-5]  75.98 111.7 270 bottom
R360  0E_1%  [RES0402_0-5]  73.72 110 270 bottom
R361  0E_1%  [RES0402_0-5]  76.02 108.73 270 bottom
R362  1K  [RES0402_0-5]  24.34 130.97 0 bottom
R363  1K  [RES0402_0-5]  24.34 132.26 0 bottom
R364  10K  [RES0402_0-5]  40.42 134.49 0 top
R365  10K  [RES0402_0-5]  40.41 131.57 0 top
R366  0E  [RES0402_0-5]  40.41 133.02 180 bottom
R367  0E  [RES0402_0-5]  40.42 134.49 180 bottom
R368  0E  [RES0402_0-5]  40.42 130.11 180 bottom
R369  0E  [RES0402_0-5]  40.41 131.57 180 bottom
R370  1K  [RES0402_0-5]  24.38 139.81 0 bottom
R371  1K  [RES0402_0-5]  24.38 141.09 0 bottom
R372  10K  [RES0402_0-5]  40.46 143.32 0 top
R373  10K  [RES0402_0-5]  40.45 140.4 0 top
R374  0E  [RES0402_0-5]  40.45 141.86 180 bottom
R375  0E  [RES0402_0-5]  40.46 143.32 180 bottom
R376  0E  [RES0402_0-5]  40.46 138.94 180 bottom
R377  0E  [RES0402_0-5]  40.45 140.4 180 bottom
R378  1K  [RES0402_0-5]  24.46 148.71 0 bottom
R379  1K  [RES0402_0-5]  24.46 149.99 0 bottom
R380  10K  [RES0402_0-5]  40.54 152.22 0 top
R381  10K  [RES0402_0-5]  40.53 149.3 0 top
R382  0E  [RES0402_0-5]  40.53 150.75 180 bottom
R383  0E  [RES0402_0-5]  40.54 152.22 180 bottom
R384  0E  [RES0402_0-5]  40.54 147.84 180 bottom
R385  0E  [RES0402_0-5]  40.53 149.3 180 bottom
R386  100K  [RES0402_0-5]  40.42 130.11 180 top
R387  100K  [RES0402_0-5]  40.41 133.02 180 top
R388  100K  [RES0402_0-5]  40.46 138.94 180 top
R389  100K  [RES0402_0-5]  40.45 141.86 180 top
R390  100K  [RES0402_0-5]  40.53 150.75 180 top
R391  100K  [RES0402_0-5]  40.54 147.84 180 top
SW2  218-2LPST  [SW4_49-99_150X230_SMD_2-7]  18.8 131.63 90 bottom
SW3  218-2LPST  [SW4_49-99_150X230_SMD_2-7]  18.84 140.47 90 bottom
SW4  218-2LPST  [SW4_49-99_150X230_SMD_2-7]  18.92 149.36 90 bottom
T1  DA2304-AL  [XFMR8_DA2303-A_320X390_SMD_6]  26.09 119.49 180 bottom
TP1  THRU HOLE  [TP_40X65]  36.96 192.8 180 bottom
TP2  THRU HOLE  [TP_40X65]  34.34 168.18 180 bottom
TP3  THRU HOLE  [TP_40X65]  38.09 123.66 90 bottom
TP4  -  [TP40_SMD]  16.75 112.14 180 bottom
TP5  -  [TP40_SMD]  18.36 103.67 180 bottom
TP6  THRU HOLE  [TP_40X65]  39.5 103.65 270 bottom
TP7  -  [TP40_SMD]  33.17 93.78 90 bottom
TP8  THRU HOLE  [TP_40X65]  59.94 92.34 270 bottom
TP9  THRU HOLE  [TP_40X65]  51.44 92.34 270 bottom
TP10  THRU HOLE  [TP_40X65]  93.86 86.81 180 bottom
TP11  -  [TP40_SMD]  32.89 83.71 90 bottom
TP12  -  [TP40_SMD]  51.44 81.29 270 bottom
TP13  -  [TP40_SMD]  51.44 71.13 270 bottom
TP14  -  [TP40_SMD]  32.82 63.13 90 bottom
TP15  -  [TP40_SMD]  32.84 52.97 90 bottom
TP16  -  [TP40_SMD]  48.51 50.31 270 bottom
TP17  -  [TP40_SMD]  48.51 40.15 270 bottom
TP18  THRU HOLE  [TP_40X65]  32.51 37.15 90 bottom
TP19  THRU HOLE  [TP_40X65]  76.38 35.8 90 bottom
TP20  THRU HOLE  [TP_40X65]  92.15 38.14 180 bottom
TP21  -  [TP40_SMD]  44.65 26.62 180 bottom
TP22  -  [TP40_SMD]  89.53 124.55 180 bottom
TP23  -  [TP40_SMD]  94.46 127.84 180 bottom
TP24  -  [TP40_SMD]  89.53 122.34 180 bottom
TP25  -  [TP40_SMD]  81.25 125.58 180 bottom
TP26  -  [TP40_SMD]  81.27 127.64 180 bottom
TP27  -  [TP40_SMD]  94.01 47.87 180 bottom
TP28  -  [TP40_SMD]  91.11 49.06 180 bottom
TP29  -  [TP40_SMD]  90.04 51.58 180 bottom
TP30  THRU HOLE  [TP_40X65]  93.55 78.88 180 bottom
TP31  -  [TP40_SMD]  84.51 75.78 180 bottom
TP32  -  [TP40_SMD]  86.74 75.78 180 bottom
TP33  -  [TP40_SMD]  50.37 67.5 180 bottom
TP34  -  [TP40_SMD]  92.53 42.94 180 bottom
TP35  -  [TP40_SMD]  94.51 44.59 180 bottom
TP36  -  [TP20_SMD]  46.74 85.99 180 bottom
TP37  -  [TP20_SMD]  46.74 84.85 180 bottom
TP38  -  [TP20_SMD]  46.74 83.71 180 bottom
TP39  -  [TP20_SMD]  46.74 82.56 180 bottom
TP40  -  [TP20_SMD]  44.18 97.44 180 bottom
TP41  -  [TP20_SMD]  46.74 87.14 180 bottom
TP42  -  [TP20_SMD]  48.65 91.69 180 bottom
TP43  -  [TP20_SMD]  47.88 92.85 180 bottom
TP44  -  [TP20_SMD]  47.88 93.99 180 bottom
TP45  -  [TP20_SMD]  46.68 95.65 180 bottom
TP46  -  [TP20_SMD]  41.91 98.65 180 bottom
TP47  -  [TP20_SMD]  47.51 89.39 180 bottom
TP48  -  [TP20_SMD]  47.98 54.12 180 bottom
TP49  -  [TP20_SMD]  46.74 54.12 180 bottom
TP50  -  [TP20_SMD]  46.74 52.97 180 bottom
TP51  -  [TP20_SMD]  46.74 51.83 180 bottom
TP52  -  [TP20_SMD]  47.88 64.4 180 bottom
TP53  -  [TP20_SMD]  46.74 56.4 180 bottom
TP54  -  [TP20_SMD]  48.63 61.23 180 bottom
TP55  -  [TP20_SMD]  49.23 63.3 180 bottom
TP56  -  [TP20_SMD]  49.05 64.42 180 bottom
TP57  -  [TP20_SMD]  47.16 65.37 180 bottom
TP58  -  [TP20_SMD]  42.16 67.58 180 bottom
TP59  -  [TP20_SMD]  49.25 62.1 180 bottom
TP60  -  [TP40_SMD]  81.28 123.56 0 top
TP61  -  [TP40_SMD]  81.28 125.57 0 top
TP62  -  [TP40_SMD]  93.71 84.29 180 bottom
TP63  -  [TP40_SMD]  93.71 81.83 180 bottom
U1  TPS76650D  [SOIC8]  17.4 116.46 90 top
U2  SN74LVC1G08DBVRE4  [SOT23-5]  28.57 97.42 90 top
U3  DP83867ERGZT  [VQFN48_19-68_285X285]  38.87 89.18 0 top
U4  SN74LVC1G08DBVRE4  [SOT23-5]  27.36 65.22 90 top
U5  DP83867ERGZT  [VQFN48_19-68_285X285]  38.87 58.44 0 top
U6  TCAN1042H-Q1  [SOIC8_1-8]  20.57 189.5 180 bottom
U7  TCAN1042H-Q1  [SOIC8_1-8]  20.57 183.4 180 bottom
U8  TCAN1042H-Q1  [SOIC8_1-8]  20.57 177.31 180 bottom
U9  TCAN1042H-Q1  [SOIC8_1-8]  20.57 171.21 180 bottom
U11  TCAN1042H-Q1  [SOIC8_1-8]  20.57 165.11 180 bottom
U12  OPA2376AIDGKR  [VSSOP8_25-59_120X120_1-1]  78.49 163.11 90 bottom
U13  OPA2376AIDGKR  [VSSOP8_25-59_120X120_1-1]  72.09 163.11 90 bottom
U14  OPA2376AIDGKR  [VSSOP8_25-59_120X120_1-1]  63.98 161.18 90 bottom
U15  TCAN1042H-Q1  [SOIC8_1-8]  20.57 159.02 180 bottom
U16  OPA2376AIDGKR  [VSSOP8_25-59_120X120_1-1]  87.38 155.44 90 bottom
U17  OPA2376AIDGKR  [VSSOP8_25-59_120X120_1-1]  81.2 155.44 90 bottom
U18  OPA2376AIDGKR  [VSSOP8_25-59_120X120_1-1]  74.96 155.44 90 bottom
U19  OPA2376AIDGKR  [VSSOP8_25-59_120X120_1-1]  68.25 155.44 90 bottom
U20  OPA2376AIDGKR  [VSSOP8_25-59_120X120_1-1]  57.53 155.44 90 bottom
U22  SN74CB3Q3257PWR  [TSSOP16_25-59_205X180]  44.96 117.74 180 bottom
U23  SN74CB3Q3257PWR  [TSSOP16_25-59_205X180]  60 117.72 180 bottom
U25  TPS74801DRCR  [VSON10_TPS74801-Q1_120X120_1]  40.51 110 270 bottom
U26  ISO1176TDW  [SOIC16_W]  26.09 106.86 180 bottom
U27  TPS74801DRCR  [VSON10_TPS74801-Q1_120X120_1]  60.96 98.69 270 bottom
U28  TPS74801DRCR  [VSON10_TPS74801-Q1_120X120_1]  52.45 98.69 270 bottom
U29  SN74CBTLV16292GR  [TSSOP56_19-68_560X240_1-2]  73.03 94.25 180 bottom
U30  DP83867ERGZT  [VQFN48_19-68_285X285]  57.41 75.83 0 bottom
U31  ICS651MLF  [SOIC8]  72.57 69.98 180 bottom
U33  SN74LVC1G08DBVRE4  [SOT23-5]  51.71 62.24 270 bottom
U34  SN74CB3Q3257PWR  [TSSOP16_25-59_205X180]  76.51 60.85 180 bottom
U35  SN74CB3Q3257PWR  [TSSOP16_25-59_205X180]  63.37 60.72 180 bottom
U36  CAT24C256WI-GT3  [SOIC8_1-8]  78.61 49.16 90 bottom
U37  DP83867ERGZT  [VQFN48_19-68_285X285]  54.49 44.84 0 bottom
U38  SN74LVC1G08DBVRE4  [SOT23-5]  46.79 34.69 270 bottom
U39  SN74LVC1G08DBVRE4  [SOT23-5]  27.14 34.68 270 bottom
U40  DP83822IRHBT  [QFN32_19-68_200X200_1]  36.64 25.36 90 bottom
U41  SN74CBTLV16292GR  [TSSOP56_19-68_560X240_1-2]  58.46 131.28 270 top
U42  SN74CB3Q3257PWR  [TSSOP16_25-59_205X180]  71.95 43.63 90 top
U44  SN74CB3Q3257PWR  [TSSOP16_25-59_205X180]  58.48 22.41 180 top
U45  TLIN1022DMTTQ1  [VSON14_25-59_120X180_0-9]  36.45 132.18 180 bottom
U46  TLIN1022DMTTQ1  [VSON14_25-59_120X180_0-9]  36.49 141.01 180 bottom
U47  TLIN1022DMTTQ1  [VSON14_25-59_120X180_0-9]  36.57 149.91 180 bottom
Y1  25.000MHz  [XTAL_ABM3_205X130_SMD_1-4]  36.96 78.25 0 top
Y2  25.000MHz  [XTAL_ABM3_205X130_SMD_1-4]  36.96 47.51 0 top
Y3  25.000MHz  [XTAL_ABM3_205X130_SMD_1-4]  55.5 86.76 0 bottom
Y4  25.000MHz  [XTAL_ABM3_205X130_SMD_1-4]  52.58 55.77 0 bottom
Y5  25.000MHz  [XTAL_ABM3_205X130_SMD_1-4]  39.43 32.98 0 bottom

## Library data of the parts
C1-C4 C6-C42 C44-C81 C83-C102 C107-C111 C113-C150 C152-C166 C168-C207 = CAP
C5 = CAP_POL
C43 C167 = CAP: signal model: INS23888586
D4 D5 = DIODE_SCHOTTKY
D6 = DIODE_SM712_TVS
D7-D18 = DIODE
FL1-FL3 = EMIFILTER_IND
J1 J2 = CON_INT_60X2_M
J3 J6 J8 J10 J12 J14 = HEADER_3X1
J4 J7 J9 J11 J13 J15 = HEADER_2X1
J5 J16 = HEADER_10X2
J18 = CON_D9F_RT_TH
J19 = RECP_5X2
J20 J21 = CON_RJ45-28_LPJG17512AONL
J22 = HEADER_8x2
J23 = CON_RJ45-14_LPJG16314A4NL
J24 = RECP_30X2
J25-J27 = HEADER_4X1
Q1-Q13 = MOSFET_2N7002_SOT23
R1-R15 R18 R21 R26 R27 R36-R57 R63 R65 R66 R77-R93 R102 R103 R105-R115 R117 R118 R121-R141 R144 R148-R152 R154 R156 R157 R159 R160 R163 R164 R166 R167 R170-R182 R194 R201-R206 R209-R216 R218-R224 R227 R228 R237-R239 R245 R247 R251-R262 R269-R271 R273-R288 R294-R301 R362-R365 R370-R373 R378-R381 R386-R391 = RESISTOR
R16 R19 R22-R25 R58 R60 R61 R64 R67 R68 R191-R193 R195 R197 R200 R240-R244 R250 R264 R266 R268 = RESISTOR: signal model: RESISTOR_RES0402_22E_1%_22E_1%
R17 R20 R28-R35 R59 R62 R69-R76 R158 R161 R162 R165 R168 R169 R183-R190 R199 R217 R225 R226 R229-R236 R246 R248 R249 R338-R361 R366-R369 R374-R377 R382-R385 = RESISTOR: signal model: INS23888567
R94 R96-R99 = RESISTOR: signal model: RESISTOR_RES0402_1.96K_1%_1.96K_1%
R95 R100 R101 R263 R265 = RESISTOR: signal model: RESISTOR_RES0402_2.49K_1%_2.49K_1%
R196 R198 R207 R208 = RESISTOR: signal model: INS23888600
R267 = RESISTOR: signal model: RESISTOR_RES0402_0-5_10K_10K
R289-R292 = RESISTOR: signal model: DEFAULT_RESISTOR_49.9OHM_1_2
SW2-SW4 = SW4_GDH02S04
T1 = TRANS_DA2303-AL
TP1-TP63 = TESTPOINT
U1 = TPS766_SOIC8
U2 U4 U33 U38 U39 = SN74LVC1G08DBVRE4_SOT23-5
U3 U5 U30 U37 = DP83867ERGZT_VQFN48
U6-U9 U11 U15 = TCAN1042HGVD_SOIC8
U12-U14 U16-U20 = OPA2350UA_SOIC8
U22 U23 U34 U35 U42 U44 = SN74CB3Q3257PWR_TSSOP16
U25 U27 U28 = TPS74801DRCR_SON10
U26 = ISO1177DW_SOIC16
U29 U41 = SN74CBTLV16292GR_TSSOP56_TI
U31 = ICS651MLF_SOIC8
U36 = CAT24C256WI-GT3_SOIC8
U40 = DP83822HF_QFN32
U45-U47 = TLIN1022DMTTQ1_VSON14
Y1-Y5 = CRY

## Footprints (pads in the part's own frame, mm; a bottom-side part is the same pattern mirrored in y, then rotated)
CAP0402_0-5
  rect 0.483x0.584 smd: 1(-0.49,0) 2(0.49,0)
CAP0402_0-75
  rect 0.559x0.635 smd: 1(-0.49,0) 2(0.49,0)
CAP0603_1
  rect 0.94x1.016 smd: 1(-0.8,0) 2(0.8,0)
CAP0805_1-5
  rect 1.143x1.448 smd: 1(-0.9,0) 2(0.9,0)
CAP1206_1-75
  rect 1.143x1.803 smd: 1(-1.5,0) 2(1.5,0)
CAP1206_2
  rect 1.143x1.803 smd: 1(-1.5,0) 2(1.5,0)
CAP1210_2-75
  rect 0.965x2.718 smd: 1(-1.65,0) 2(1.65,0)
CAPT3216A_2
  rect 1.803x1.295 smd: 1(-1.3,0) 2(1.3,0)
CON_DB9_D09S33E4GV_S_R_T
  rect 1.6x1.6 hole 0.914: 1(0,0)
  round 1.6 hole 0.914: 2(-2.74,0) 3(-5.48,0) 4(-8.22,0) 5(-10.96,0) 6(-1.37,-2.84) 7(-4.11,-2.84) 8(-6.85,-2.84) 9(-9.59,-2.84)
  round 5.994 hole 3.2: 10(-17.975,-1.42) 11(7.015,-1.42)
CON_PMC2X60_QTH-60-1-D-A_P_S_S_4-4
  round 0.889 hole 1.016 unplated: (-19.24,2.03) (19.239,2.03)
  rect 0.305x1.448 smd: 1(-17.251,3.08) 2(-17.251,-3.086) 3(-16.751,3.08) 4(-16.751,-3.086) 5(-16.251,3.08) 6(-16.251,-3.086) 7(-15.751,3.08) 8(-15.751,-3.086) 9(-15.251,3.08) 10(-15.251,-3.086) 11(-14.751,3.08) 12(-14.751,-3.086) 13(-14.251,3.08) 14(-14.251,-3.086) 15(-13.751,3.08) 16(-13.751,-3.086) 17(-13.251,3.08) 18(-13.251,-3.086) 19(-12.751,3.08) 20(-12.751,-3.086) 21(-12.251,3.08) 22(-12.251,-3.086) 23(-11.751,3.08) 24(-11.751,-3.086) 25(-11.251,3.08) 26(-11.251,-3.086) 27(-10.751,3.08) 28(-10.751,-3.086) 29(-10.251,3.08) 30(-10.251,-3.086) 31(-9.751,3.08) 32(-9.751,-3.086) 33(-9.251,3.08) 34(-9.251,-3.086) 35(-8.751,3.08) 36(-8.751,-3.086) 37(-8.251,3.08) 38(-8.251,-3.086) 39(-7.751,3.08) 40(-7.751,-3.086) 41(-7.251,3.08) 42(-7.251,-3.086) 43(-6.751,3.08) 44(-6.751,-3.086) 45(-6.251,3.08) 46(-6.251,-3.086) 47(-5.751,3.08) 48(-5.751,-3.086) 49(-5.251,3.08) 50(-5.251,-3.086) 51(-4.751,3.08) 52(-4.751,-3.086) 53(-4.251,3.08) 54(-4.251,-3.086) 55(-3.751,3.08) 56(-3.751,-3.086) 57(-3.251,3.08) 58(-3.251,-3.086) 59(-2.751,3.08) 60(-2.751,-3.086) 61(2.751,3.08) 62(2.751,-3.086) 63(3.251,3.08) 64(3.251,-3.086) 65(3.751,3.08) 66(3.751,-3.086) 67(4.251,3.08) 68(4.251,-3.086) 69(4.751,3.08) 70(4.751,-3.086) 71(5.251,3.08) 72(5.251,-3.086) 73(5.751,3.08) 74(5.751,-3.086) 75(6.251,3.08) 76(6.251,-3.086) 77(6.751,3.08) 78(6.751,-3.086) 79(7.251,3.08) 80(7.251,-3.086) 81(7.751,3.08) 82(7.751,-3.086) 83(8.251,3.08) 84(8.251,-3.086) 85(8.751,3.08) 86(8.751,-3.086) 87(9.251,3.08) 88(9.251,-3.086) 89(9.751,3.08) 90(9.751,-3.086) 91(10.251,3.08) 92(10.251,-3.086) 93(10.751,3.08) 94(10.751,-3.086) 95(11.251,3.08) 96(11.251,-3.086) 97(11.751,3.08) 98(11.751,-3.086) 99(12.251,3.08) 100(12.251,-3.086) 101(12.751,3.08) 102(12.751,-3.086) 103(13.251,3.08) 104(13.251,-3.086) 105(13.751,3.08) 106(13.751,-3.086) 107(14.251,3.08) 108(14.251,-3.086) 109(14.751,3.08) 110(14.751,-3.086) 111(15.251,3.08) 112(15.251,-3.086) 113(15.751,3.08) 114(15.751,-3.086) 115(16.251,3.08) 116(16.251,-3.086) 117(16.751,3.08) 118(16.751,-3.086) 119(17.251,3.08) 120(17.251,-3.086)
  rect 2.54x0.635 smd: 121(-18.441,0) 124(-1.551,0) 125(1.561,0) 128(18.451,0)
  rect 4.699x0.635 smd: 122(-13.172,0) 123(-6.822,0) 126(6.832,0) 127(13.182,0)
CON_RJ45-14_LPJG16314A4NL_S_R_T_13-6
  round 3.073 hole 3.2 unplated: (0,-8.89) (11.43,-8.89)
  rect 1.6x1.6 hole 0.914: 1(0,0)
  round 1.6 hole 0.914: 2(1.27,-2.54) 3(2.54,0) 4(3.81,-2.54) 5(5.08,0) 6(6.35,-2.54) 7(7.62,0) 8(8.89,-2.54) 9(10.16,0) 10(11.43,-2.54)
  round 1.702 hole 1.016: 11(12.44,-11.43) 12(12.44,-13.462) 13(-1.01,-11.43) 14(-1.01,-13.462)
  round 2.362 hole 1.676: 15(-2.032,-5.842) 16(13.462,-5.842)
CON_RJ45-28_LPJG17512_S_R_T_25-3
  round 3.073 hole 3.2 unplated: (-2.42,-4.71) (9.01,-4.71)
  round 1.6 hole 0.914: A1(0,0) A2(1.27,1.27) A3(0,2.54) A4(1.27,3.81) A5(0,5.08) A6(1.27,6.35) A7(0,7.62) A8(1.27,8.89) A9(0,10.16) A10(1.27,11.43) A11(6.34,-3.7) A12(4.31,-3.7) A13(2.28,-3.7) A14(0.25,-3.7) B1(6.6,0) B2(5.33,1.27) B3(6.6,2.54) B4(5.33,3.81) B5(6.6,5.08) B6(5.33,6.35) B7(6.6,7.62) B8(5.33,8.89) B9(6.6,10.16) B10(5.33,11.43) B11(6.34,-1.85) B12(4.31,-1.85) B13(2.28,-1.85) B14(0.25,-1.85)
  round 2.362 hole 1.676: SH1(-5.21,10.78) SH2(11.8,6.72) SH3(-5.21,-9.28) SH4(11.8,-9.28)
DIO_SOD123
  rect 1.016x0.813 smd: 1(-1.8,0) 2(1.8,0)
DIO_SOD123_1-4
  rect 1.016x0.813 smd: 1(-1.8,0) 2(1.8,0)
DIO_SOT23_123
  rect 1.016x0.61 smd: 1(-1.15,0.95) 2(-1.15,-0.95) 3(1.15,0)
EMIFIL_BLM15A_0402_0-6
  rect 0.508x0.508 smd: 1(-0.46,0) 2(0.46,0)
EMIFIL_BLM18A_0603
  rect 0.991x0.991 smd: 1(-0.75,0) 2(0.75,0)
HDR_1X2_68002-202_S_T_8-6
  rect 1.702x1.702 hole 1.016: 1(0,0)
  round 1.702 hole 1.016: 2(-2.54,0)
HDR_1X4_61300411121_S_T_8-6
  rect 1.803x1.803 hole 1.118: 1(0,0)
  round 1.803 hole 1.118: 2(-2.54,0) 3(-5.08,0) 4(-7.62,0)
HDR_2X10_TSW_100_S_T
  rect 1.702x1.702 hole 1.016: 1(0,0)
  round 1.702 hole 1.016: 2(0,-2.54) 3(-2.54,0) 4(-2.54,-2.54) 5(-5.08,0) 6(-5.08,-2.54) 7(-7.62,0) 8(-7.62,-2.54) 9(-10.16,0) 10(-10.16,-2.54) 11(-12.7,0) 12(-12.7,-2.54) 13(-15.24,0) 14(-15.24,-2.54) 15(-17.78,0) 16(-17.78,-2.54) 17(-20.32,0) 18(-20.32,-2.54) 19(-22.86,0) 20(-22.86,-2.54)
HDR_3X1_100_S_T
  rect 1.803x1.803 hole 1.118: 1(0,0)
  round 1.803 hole 1.118: 2(-2.54,0) 3(-5.08,0)
HDR_8X2_100_S_T
  rect 1.803x1.803 hole 1.118: 1(0,0)
  round 1.803 hole 1.118: 2(0,-2.54) 3(-2.54,0) 4(-2.54,-2.54) 5(-5.08,0) 6(-5.08,-2.54) 7(-7.62,0) 8(-7.62,-2.54) 9(-10.16,0) 10(-10.16,-2.54) 11(-12.7,0) 12(-12.7,-2.54) 13(-15.24,0) 14(-15.24,-2.54) 15(-17.78,0) 16(-17.78,-2.54)
QFN32_19-68_200X200_1
  rect 0.838x0.305 smd: 1(-2.5,1.75) 2(-2.5,1.25) 3(-2.5,0.75) 4(-2.5,0.25) 5(-2.5,-0.25) 6(-2.5,-0.75) 7(-2.5,-1.25) 8(-2.5,-1.75) 17(2.5,-1.75) 18(2.5,-1.25) 19(2.5,-0.75) 20(2.5,-0.25) 21(2.5,0.25) 22(2.5,0.75) 23(2.5,1.25) 24(2.5,1.75)
  rect 0.305x0.838 smd: 9(-1.75,-2.5) 10(-1.25,-2.5) 11(-0.75,-2.5) 12(-0.25,-2.5) 13(0.25,-2.5) 14(0.75,-2.5) 15(1.25,-2.5) 16(1.75,-2.5) 25(1.75,2.5) 26(1.25,2.5) 27(0.75,2.5) 28(0.25,2.5) 29(-0.25,2.5) 30(-0.75,2.5) 31(-1.25,2.5) 32(-1.75,2.5)
  rect 3.556x3.556 smd: 33(0,0)
RECPT_2X5_NPPN052AFCN_S_T_4-3
  rect 1.499x1.499 hole 0.813: 1(0,0)
  round 1.499 hole 0.813: 2(0,-2) 3(2,0) 4(2,-2) 5(4,0) 6(4,-2) 7(6,0) 8(6,-2) 9(8,0) 10(8,-2)
RECPT_2X30_78-74_S_T
  rect 1.6x1.6 hole 0.914: 1(0,0)
  round 1.6 hole 0.914: 2(0,2) 3(-2,0) 4(-2,2) 5(-4,0) 6(-4,2) 7(-6,0) 8(-6,2) 9(-8,0) 10(-8,2) 11(-10,0) 12(-10,2) 13(-12,0) 14(-12,2) 15(-14,0) 16(-14,2) 17(-16,0) 18(-16,2) 19(-18,0) 20(-18,2) 21(-20,0) 22(-20,2) 23(-22,0) 24(-22,2) 25(-24,0) 26(-24,2) 27(-26,0) 28(-26,2) 29(-28,0) 30(-28,2) 31(-30,0) 32(-30,2) 33(-32,0) 34(-32,2) 35(-34,0) 36(-34,2) 37(-36,0) 38(-36,2) 39(-38,0) 40(-38,2) 41(-40,0) 42(-40,2) 43(-42,0) 44(-42,2) 45(-44,0) 46(-44,2) 47(-46,0) 48(-46,2) 49(-48,0) 50(-48,2) 51(-50,0) 52(-50,2) 53(-52,0) 54(-52,2) 55(-54,0) 56(-54,2) 57(-56,0) 58(-56,2) 59(-58,0) 60(-58,2)
